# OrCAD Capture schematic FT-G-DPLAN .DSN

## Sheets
1 INDEX: size A; title: INDEX; rev: 1.11; note: 188C03322
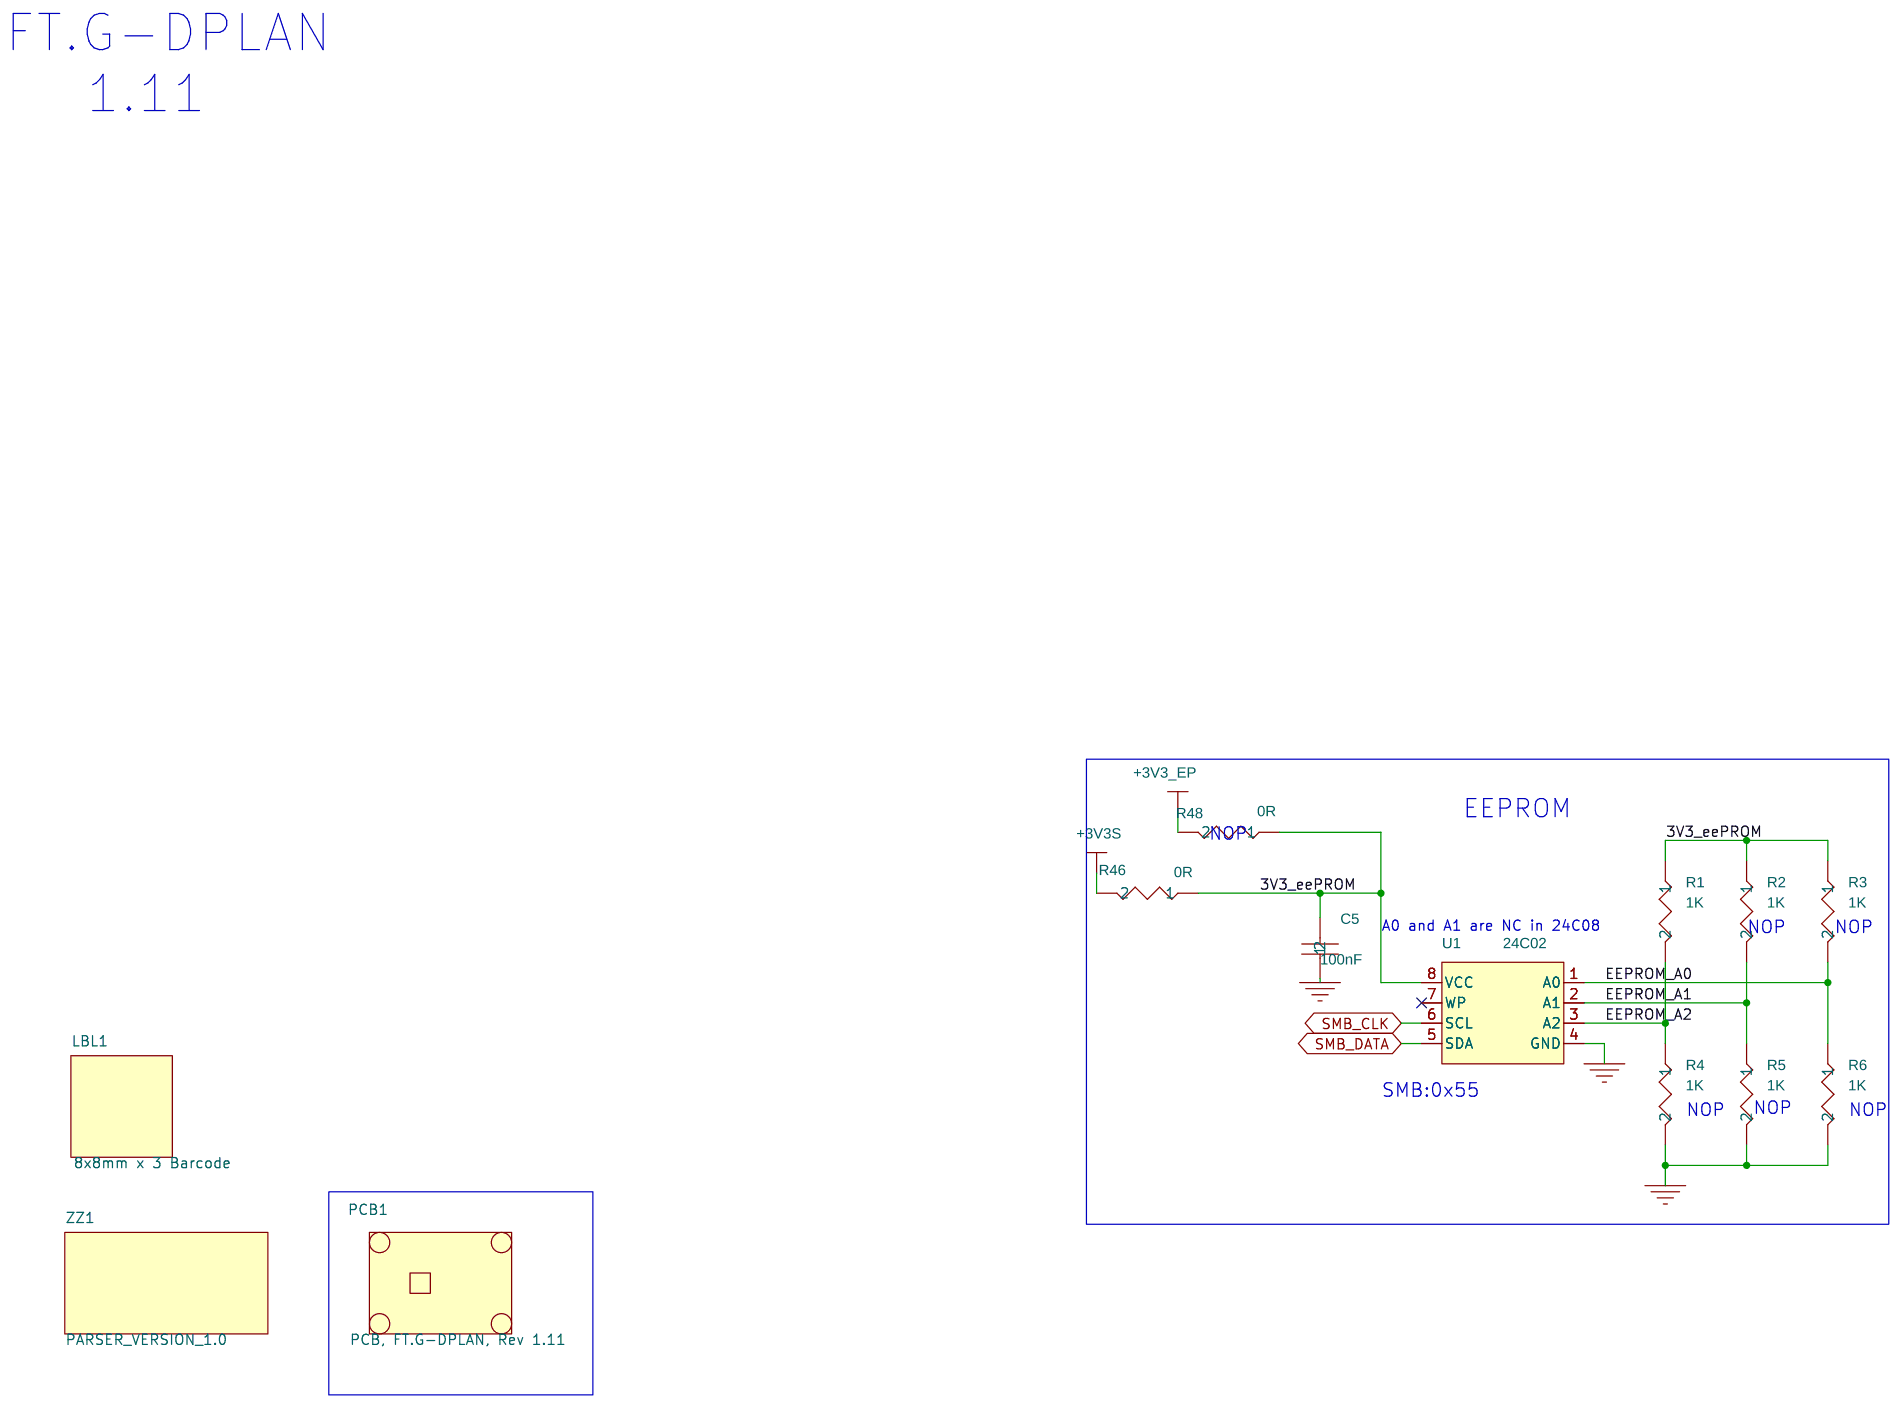
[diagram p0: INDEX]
2 Ribbon Conn.: size A; title: Ribbon Conn
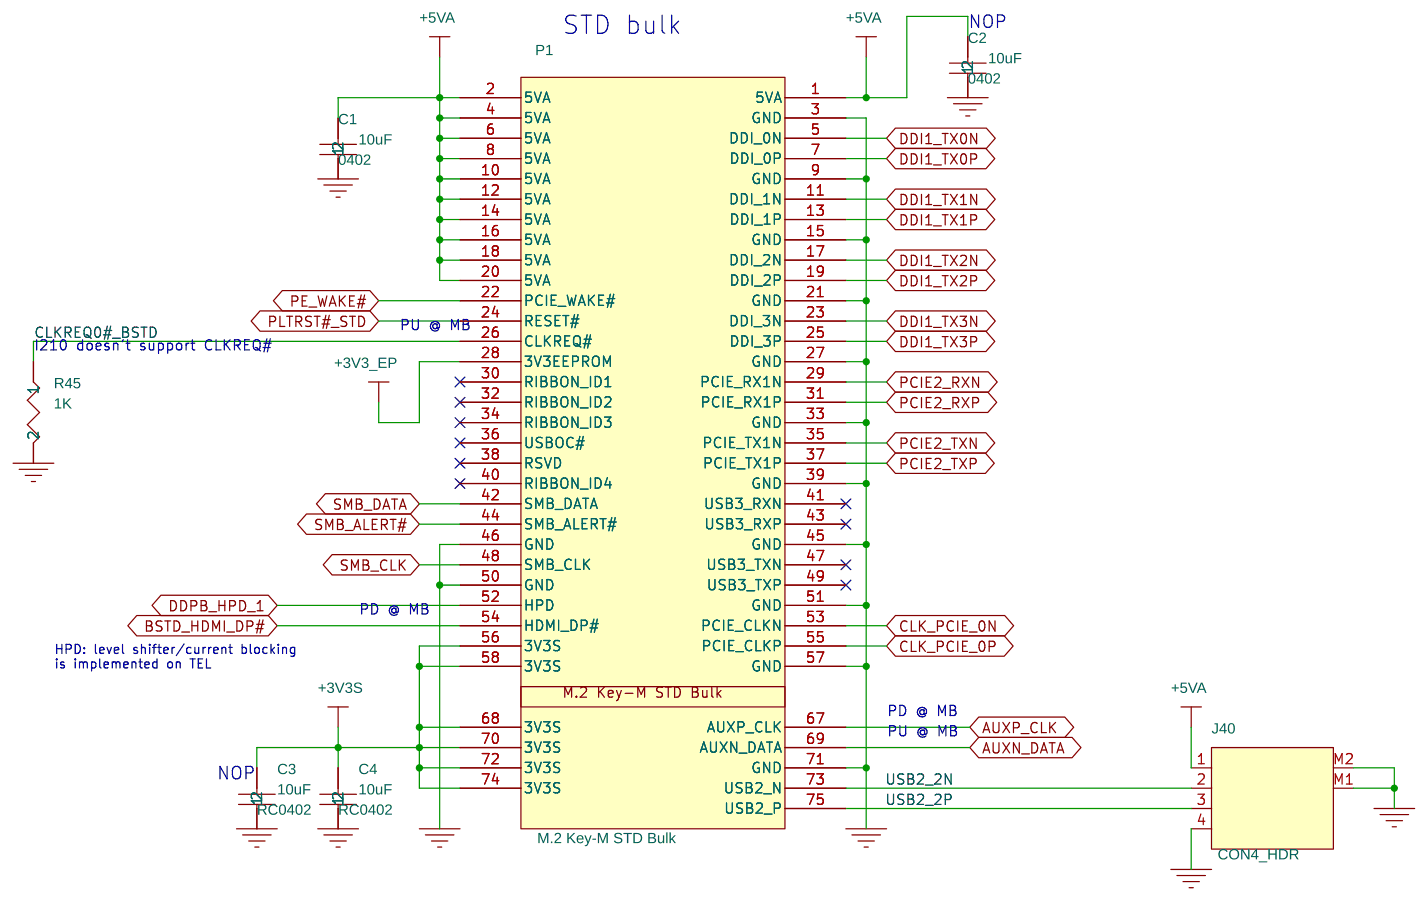
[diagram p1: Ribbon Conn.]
3 LAN: size A2; title: LAN
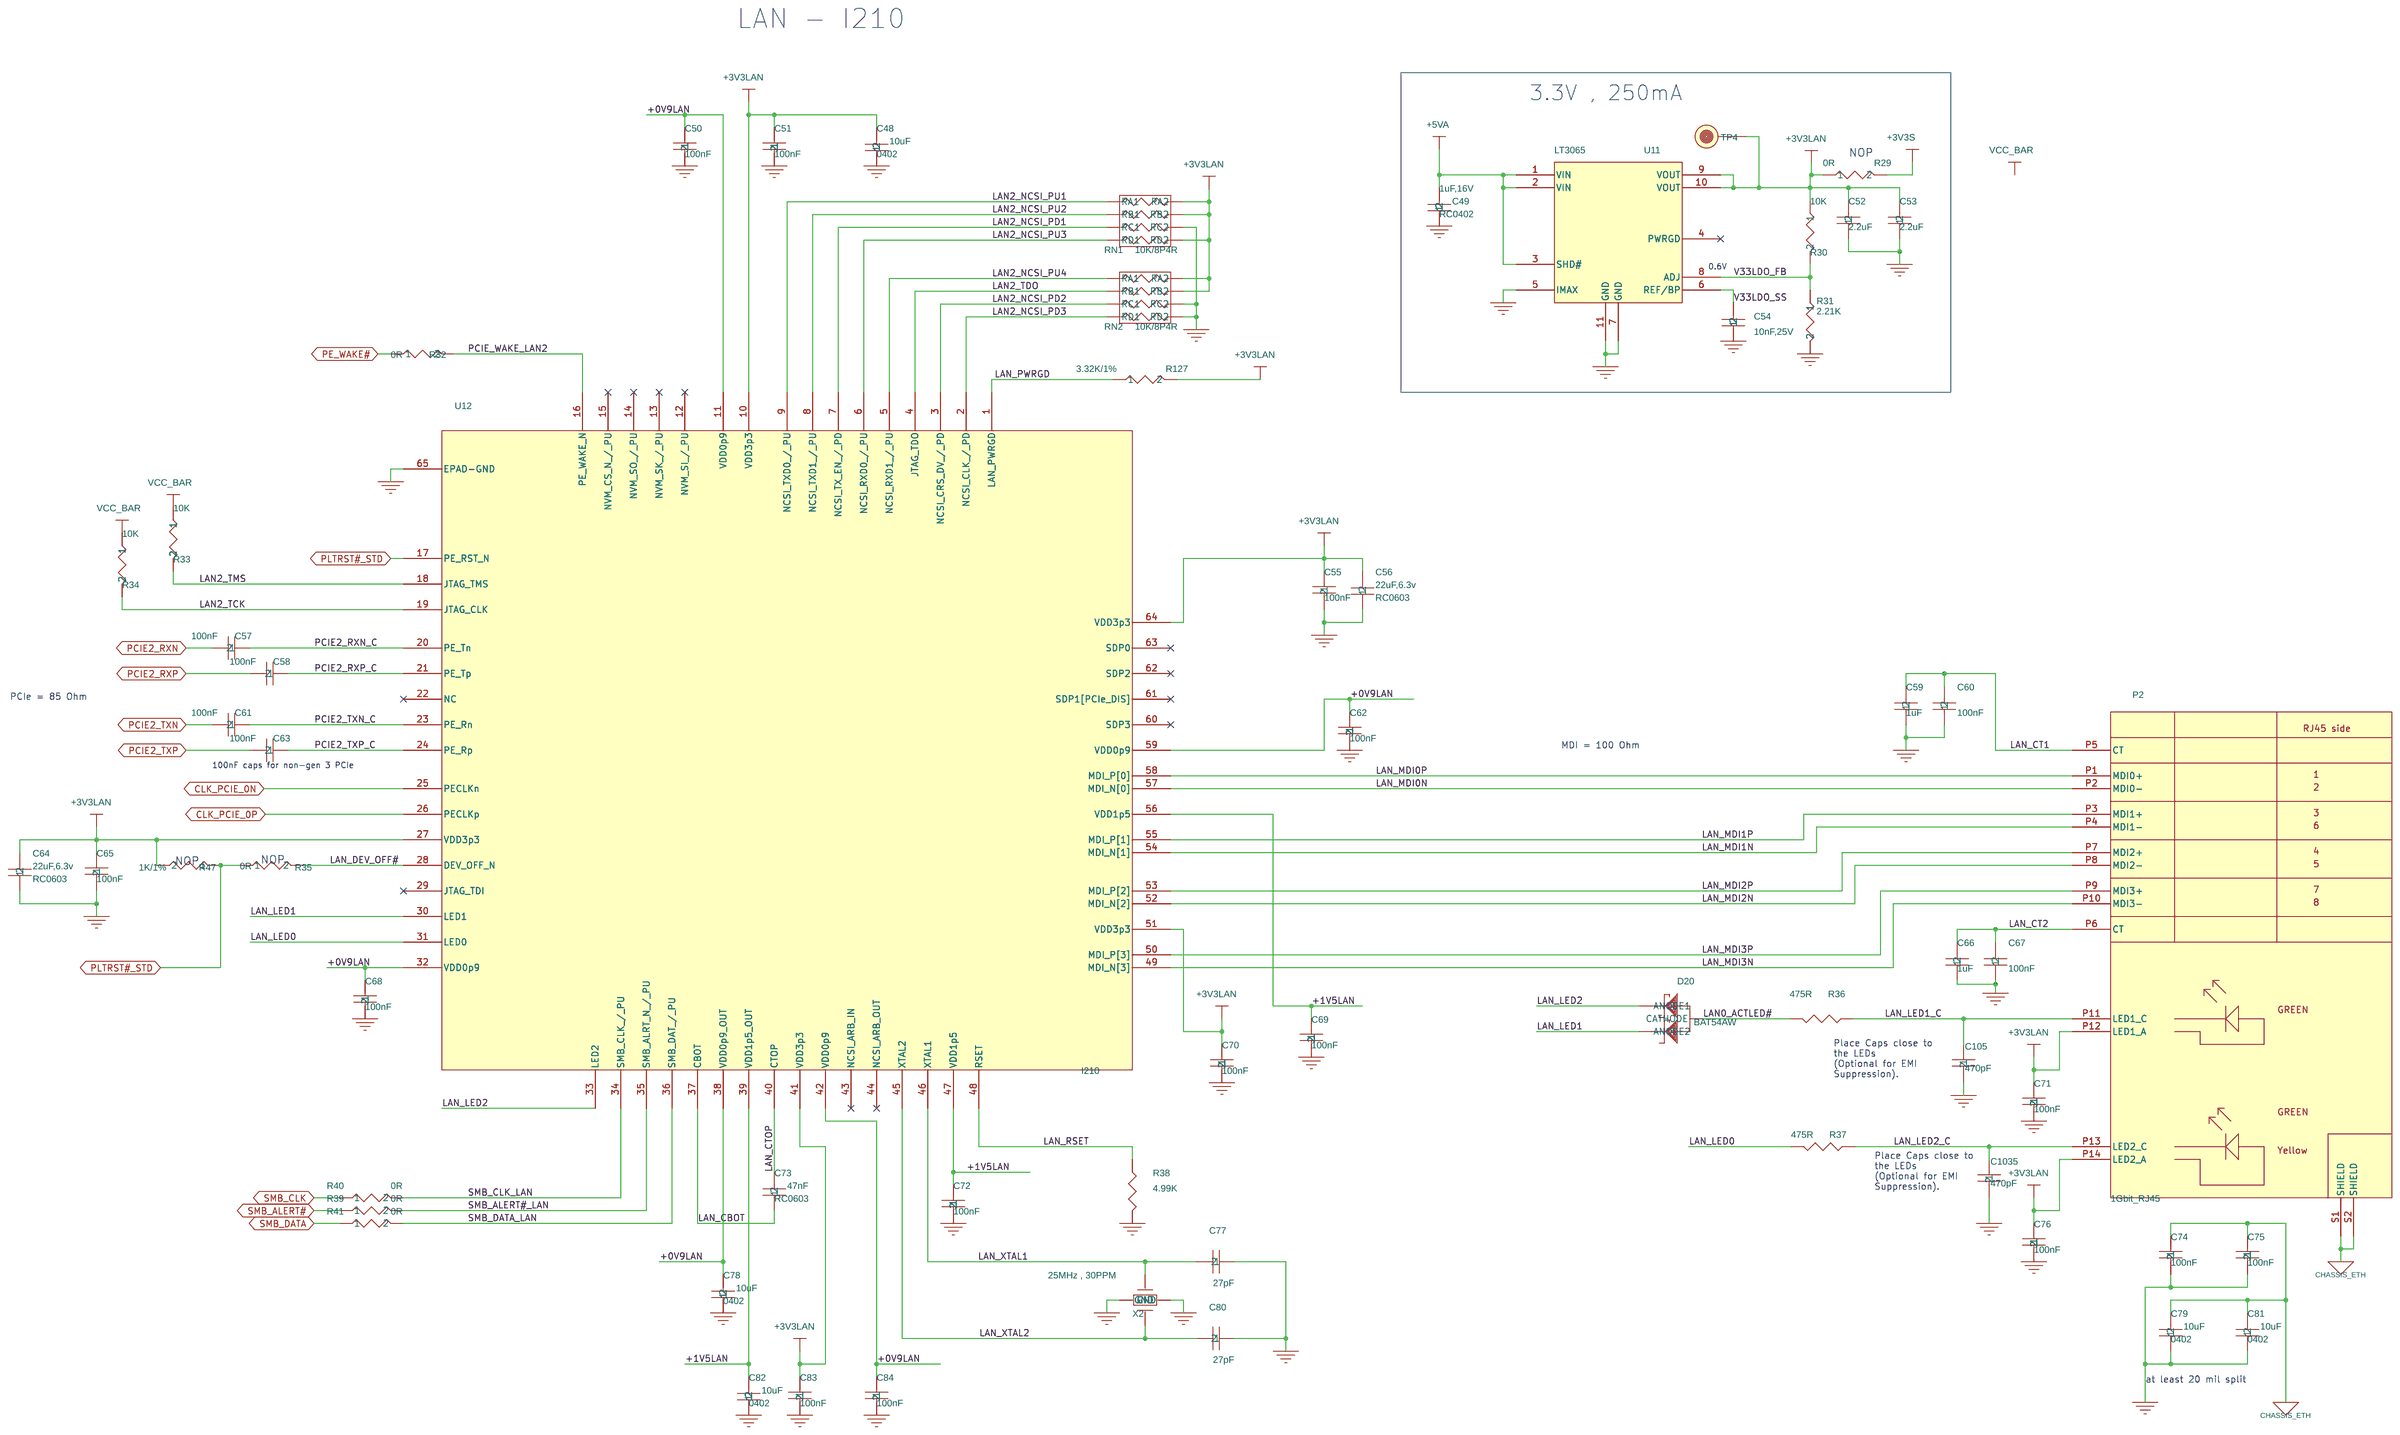
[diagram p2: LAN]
4 DP: size A4; title: DP
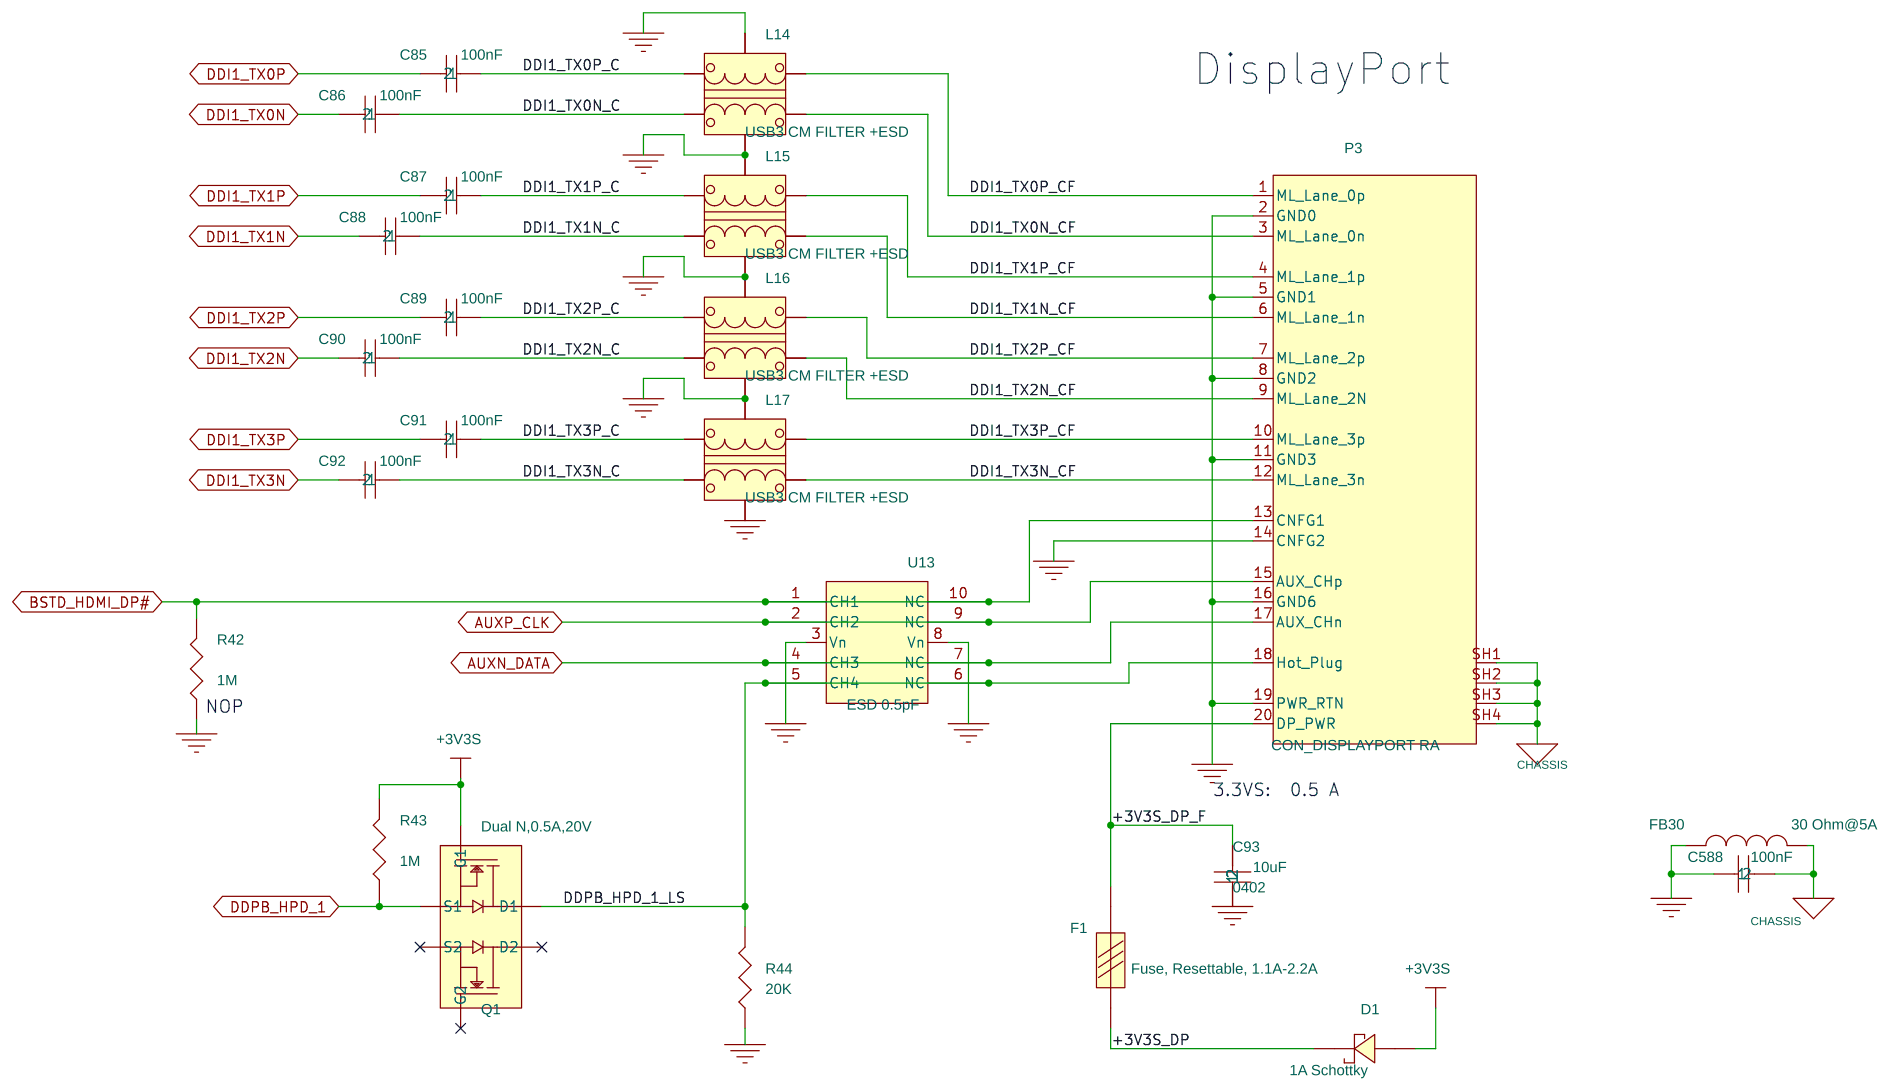
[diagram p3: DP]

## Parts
sheet DP
C85  100nF  [RC0402]
C86  100nF  [RC0402]
C87  100nF  [RC0402]
C88  100nF  [RC0402]
C89  100nF  [RC0402]
C90  100nF  [RC0402]
C91  100nF  [RC0402]
C92  100nF  [RC0402]
C93  10uF  [0402]
C588  100nF  [RC0402]
D1  1A Schottky  [SOD-123]
F1  Fuse, Resettable, 1.1A-2.2A  [FUSE-1206]
FB30  30 Ohm@5A  [FB0603]
L14  USB3 CM FILTER +ESD  [EMI1012-ESD]
L15  USB3 CM FILTER +ESD  [EMI1012-ESD]
L16  USB3 CM FILTER +ESD  [EMI1012-ESD]
L17  USB3 CM FILTER +ESD  [EMI1012-ESD]
P3  CON_DISPLAYPORT RA  [DP-F-RA-SM]
Q1  Dual N,0.5A,20V  [SOT-563-6]
R42  1M  [RC0402]
R43  1M  [RC0402]
R44  20K  [RC0402]
U13  ESD 0.5pF  [DFN-X2510D-10]
sheet INDEX
C5  100nF  [RC0402]
LBL1  8x8mm x 3 Barcode  [LBL XYU]
PCB1  PCB, FT.G-DPLAN, Rev 1.11
R1  1K  [RC0402]
R2  1K  [RC0402]
R3  1K  [RC0402]
R4  1K  [RC0402]
R5  1K  [RC0402]
R6  1K  [RC0402]
R46  0R  [RC0402]
R48  0R  [RC0402]
U1  24C02  [MO-229VCED-2]
ZZ1  PARSER_VERSION_1.0
sheet LAN
C48  10uF  [0402]
C49  1uF,16V  [RC0402]
C50  100nF  [RC0402]
C51  100nF  [RC0402]
C52  2.2uF  [RC0402]
C53  2.2uF  [RC0402]
C54  10nF,25V  [RC0402]
C55  100nF  [RC0402]
C56  22uF,6.3v  [RC0603]
C57  100nF  [RC0402]
C58  100nF  [RC0402]
C59  1uF  [RC0402]
C60  100nF  [RC0402]
C61  100nF  [RC0402]
C62  100nF  [RC0402]
C63  100nF  [RC0402]
C64  22uF,6.3v  [RC0603]
C65  100nF  [RC0402]
C66  1uF  [RC0402]
C67  100nF  [RC0402]
C68  100nF  [RC0402]
C69  100nF  [RC0402]
C70  100nF  [RC0402]
C71  100nF  [RC0402]
C72  100nF  [RC0402]
C73  47nF  [RC0603]
C74  100nF  [RC0402]
C75  100nF  [RC0402]
C76  100nF  [RC0402]
C77  27pF  [RC0402]
C78  10uF  [0402]
C79  10uF  [0402]
C80  27pF  [RC0402]
C81  10uF  [0402]
C82  10uF  [0402]
C83  100nF  [RC0402]
C84  100nF  [RC0402]
C105  470pF  [RC0603]
C1035  470pF  [RC0603]
D20  BAT54AW  [SOT323]
P2  1Gbit_RJ45  [DUSBRJ-1G]
R29  0R  [RC0402]
R30  10K  [RC0402]
R31  2.21K  [RC0402]
R32  0R  [RC0402]
R33  10K  [RC0402]
R34  10K  [RC0402]
R35  0R  [RC0402]
R36  475R  [RC0402]
R37  475R  [RC0402]
R38  4.99K  [RC0402]
R39  0R  [RC0402]
R40  0R  [RC0402]
R41  0R  [RC0402]
R47  1K/1%  [RC0402]
R127  3.32K/1%  [RC0402]
RN1  10K/8P4R  [RESNET8P0805]
RN2  10K/8P4R  [RESNET8P0805]
TP4  TP
U11  LT3065  [DFN3x3-10]
U12  I210  [QFN-64]
X2  25MHz , 30PPM  [OSC3225]
sheet Ribbon Conn.
C1  10uF  [0402]
C2  10uF  [0402]
C3  10uF  [RC0402]
C4  10uF  [RC0402]
J40  CON4_HDR  [1x4W2B1_25RASM]
P1  M.2 Key-M STD Bulk  [NGFF67P8HMkeySM]
R45  1K  [RC0402]

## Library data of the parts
C74 C85 = 15pF,_50V,_NPO,_5%,_0402_2: CLABCONF0: =FT-G-DPLAN; P/N: 151B10400S
C86 = 15pF,_50V,_NPO,_5%,_0402_5: CLABCONF0: =FT-G-DPLAN; P/N: 151B10400S
C75 C87 = 15pF,_50V,_NPO,_5%,_0402_6: CLABCONF0: =FT-G-DPLAN; P/N: 151B10400S
C76 C88 = 15pF,_50V,_NPO,_5%,_0402_7: CLABCONF0: =FT-G-DPLAN; P/N: 151B10400S
C5 C83 C89 = 15pF,_50V,_NPO,_5%,_0402: CLABCONF0: =FT-G-DPLAN; P/N: 151B10400S
C90 = 15pF,_50V,_NPO,_5%,_0402_1: CLABCONF0: =FT-G-DPLAN; P/N: 151B10400S
C72 C91 = 15pF,_50V,_NPO,_5%,_0402_3: CLABCONF0: =FT-G-DPLAN; P/N: 151B10400S
C71 C92 = 15pF,_50V,_NPO,_5%,_0402_4: CLABCONF0: =FT-G-DPLAN; P/N: 151B10400S
C4 C93 = 100nF,_10V,_X7R,_10%,_0402_1: CLABCONF0: =FT-G-DPLAN; P/N: 151B10600S
C588 = 100nF,_10V,_X7R,_10%,_0402: CLABCONF0: =FT-G-DPLAN
D1 = 1A_Schottky_Barrier_Rectifier: CLABCONF0: =FT-G-DPLAN
F1 = Fuse,_1.1_A_Ih,_2.2A_It: CLABCONF0: =FT-G-DPLAN
FB30 = Ferrite_bead_,_30_Ohm@5A: CLABCONF0: =FT-G-DPLAN
L14-L17 = USB3_CHOKE_+_ESD_FILTER: CLABCONF0: =FT-G-DPLAN; P/N: 142D11801S
P3 = CON_DISPLAYPORT-SINGLE_0: Con, DisplayPort single; CLABCONF0: =FT-G-DPLAN; P/N: 180K02000S
Q1 = DUAL_N-MOSFET,_0.5A_20V: CLABCONF0: =FT-G-DPLAN
R42 = RESISTOR: CLABCONF0: =NOP; P/N: 161C10045S
R43 = RESISTOR: CLABCONF0: =FT-G-DPLAN; P/N: 161C10045S
R44 = RESISTOR: CLABCONF0: =FT-G-DPLAN; P/N: 161C20021S
U13 = IC,ESD_Diode,0.25pF_,x4: CLABCONF0: =FT-G-DPLAN; P/N: 132D10020S
LBL1 = Label_8x8mm_x_3_for_Barcode: CLABCONF0: =FT-G-DPLAN; P/N: 374F09P20CU
PCB1 = SBC-iHSW_Rev_1.0: CLABCONF0: =FT-G-DPLAN; P/N: 188C03322
R1 = 348R,1%,0402,1_16W_1: CLABCONF0: =FT-G-DPLAN; P/N: 161C10011S
R2 = 348R,1%,0402,1_16W: CLABCONF0: =NOP; P/N: 161C10011S
R3 = 348R,1%,0402,1_16W_4: CLABCONF0: =NOP; P/N: 161C10011S
R4 = 348R,1%,0402,1_16W_5: CLABCONF0: =NOP; P/N: 161C10011S
R5 = 348R,1%,0402,1_16W_3: CLABCONF0: =NOP; P/N: 161C10011S
R6 = 348R,1%,0402,1_16W_2: CLABCONF0: =NOP; P/N: 161C10011S
R46 = 0R: CLABCONF0: =NOP; P/N: 161C00005S
R48 = 0R_1: CLABCONF0: =FT-G-DPLAN; P/N: 161C00005S
U1 = 24C02,_serial_EE,_2KB,_I2C: CLABCONF0: =FT-G-DPLAN; P/N: 111S31000S
ZZ1 = PARSER_VERSION_1.0: CLABCONF0: =FT-G-DPLAN
C48 = 100nF,_10V,_X7R,_10%,_0402_12: CLABCONF0: =FT-G-DPLAN; P/N: 151B10600S
C49 = 100nF,_10V,_X7R,_10%,_0402_1: CLABCONF0: =FT-G-DPLAN; P/N: 151C10500S
C50 = 15pF,_50V,_NPO,_5%,_0402_10: CLABCONF0: =FT-G-DPLAN; P/N: 151B10400S
C51 = 15pF,_50V,_NPO,_5%,_0402_15: CLABCONF0: =FT-G-DPLAN; P/N: 151B10400S
C52 = 100nF,_10V,_X7R,_10%,_0402_16: CLABCONF0: =FT-G-DPLAN; P/N: 151A22500S
C53 = 100nF,_10V,_X7R,_10%,_0402_13: CLABCONF0: =FT-G-DPLAN; P/N: 151A22500S
C54 = 100nF,_10V,_X7R,_10%,_0402_6: CLABCONF0: =FT-G-DPLAN; P/N: 151C10300S
C55 = 15pF,_50V,_NPO,_5%,_0402_11: CLABCONF0: =FT-G-DPLAN; P/N: 151B10400S
C56 = 100nF,_10V,_X7R,_10%,_0402: CLABCONF0: =FT-G-DPLAN; P/N: 151B22610S
C57 = 100nF,_10V,_X7R,_10%,_0402_7: CLABCONF0: =FT-G-DPLAN; P/N: 151B10400S
C58 = 100nF,_10V,_X7R,_10%,_0402_11: CLABCONF0: =FT-G-DPLAN; P/N: 151B10400S
C59 = 100nF,_10V,_X7R,_10%,_0402_18: CLABCONF0: =FT-G-DPLAN; P/N: 151C10500S
C60 = 100nF,_10V,_X7R,_10%,_0402_15: CLABCONF0: =FT-G-DPLAN; P/N: 151B10400S
C61 = 100nF,_10V,_X7R,_10%,_0402_4: CLABCONF0: =FT-G-DPLAN; P/N: 151B10400S
C62 = 15pF,_50V,_NPO,_5%,_0402_8: CLABCONF0: =FT-G-DPLAN; P/N: 151B10400S
C63 = 100nF,_10V,_X7R,_10%,_0402_9: CLABCONF0: =FT-G-DPLAN; P/N: 151B10400S
C64 = 100nF,_10V,_X7R,_10%,_0402_2: CLABCONF0: =FT-G-DPLAN; P/N: 151B22610S
C65 = 15pF,_50V,_NPO,_5%,_0402_12: CLABCONF0: =FT-G-DPLAN; P/N: 151B10400S
C66 = 100nF,_10V,_X7R,_10%,_0402_14: CLABCONF0: =FT-G-DPLAN; P/N: 151C10500S
C67 = 100nF,_10V,_X7R,_10%,_0402_19: CLABCONF0: =FT-G-DPLAN; P/N: 151B10400S
C68 = 15pF,_50V,_NPO,_5%,_0402_16: CLABCONF0: =FT-G-DPLAN; P/N: 151B10400S
C69 = 15pF,_50V,_NPO,_5%,_0402_13: CLABCONF0: =FT-G-DPLAN; P/N: 151B10400S
C70 = 15pF,_50V,_NPO,_5%,_0402_9: CLABCONF0: =FT-G-DPLAN; P/N: 151B10400S
C73 = 100nF,_10V,_X7R,_10%,_0402_8: CLABCONF0: =FT-G-DPLAN; P/N: 151C47310S
C77 = 15pF,_50V,_NPO,_5%,_0402_1: CLABCONF0: =FT-G-DPLAN; P/N: 151D27000S
C78 = 100nF,_10V,_X7R,_10%,_0402_5: CLABCONF0: =FT-G-DPLAN; P/N: 151B10600S
C79 = 100nF,_10V,_X7R,_10%,_0402_17: CLABCONF0: =FT-G-DPLAN; P/N: 151B10600S
C80 = 15pF,_50V,_NPO,_5%,_0402_5: CLABCONF0: =FT-G-DPLAN; P/N: 151D27000S
C81 = 100nF,_10V,_X7R,_10%,_0402_10: CLABCONF0: =FT-G-DPLAN; P/N: 151B10600S
C82 = 100nF,_10V,_X7R,_10%,_0402_3: CLABCONF0: =FT-G-DPLAN; P/N: 151B10600S
C84 = 15pF,_50V,_NPO,_5%,_0402_14: CLABCONF0: =FT-G-DPLAN; P/N: 151B10400S
C105 = 470pF,_50V,_X7R,_10%,_0603: CLABCONF0: =FT-G-DPLAN
C1035 = 470pF,_50V,_X7R,_10%,_0603_1: CLABCONF0: =FT-G-DPLAN
D20 = BAT54AW: CLABCONF0: =FT-G-DPLAN
P2 = Con_1.,1GBit_RJ45,_short: CLABCONF0: =FT-G-DPLAN; P/N: 182K01600
R29 = 0R_2: CLABCONF0: =NOP; P/N: 161C00005S
R30 = 0R_5: CLABCONF0: =FT-G-DPLAN; P/N: 161C10021S
R31 = 0R_4: CLABCONF0: =FT-G-DPLAN; P/N: 161C22111S
R32 = 0R_7: CLABCONF0: =FT-G-DPLAN; OriginalSymbolOrigin: 100uF
R33 = 0R_1: CLABCONF0: =FT-G-DPLAN; P/N: 161C10021S
R34 = 0R: CLABCONF0: =FT-G-DPLAN; P/N: 161C10021S
R35 = 0R_9: CLABCONF0: =NOP; OriginalSymbolOrigin: 100uF
R36 R37 = RESISTOR: CLABCONF0: =FT-G-DPLAN; P/N: 161C47501S
R38 = RESISTOR: CLABCONF0: =FT-G-DPLAN; P/N: 161C49911S
R39 = 0R_8: CLABCONF0: =FT-G-DPLAN
R40 = 0R_6: CLABCONF0: =FT-G-DPLAN
R41 = 0R_3: CLABCONF0: =FT-G-DPLAN; OriginalSymbolOrigin: 100uF
R47 = 1K,1%,0402,1_16W: CLABCONF0: =NOP
R127 = 3.32K,1%,0402,1_16W: CLABCONF0: =FT-G-DPLAN
RN1 RN2 = RN,10K,8P4R@0805: CLABCONF0: =FT-G-DPLAN
TP4 = TP_SMT: CLABCONF0: =NOP
U11 = LT3065_0: CLABCONF0: =FT-G-DPLAN; P/N: 123M0R601S
U12 = IC,_I211_I210_,LAN_CONTROLLER: CLABCONF0: =FT-G-DPLAN; P/N: 116B00071S
X2 = TMP_133032: CLABCONF0: =FT-G-DPLAN; P/N: 141B25603I
C1 = 100nF,_10V,_X7R,_10%,_0402: CLABCONF0: =FT-G-DPLAN; P/N: 151B10600S
C2 = 100nF,_10V,_X7R,_10%,_0402_3: CLABCONF0: =NOP; P/N: 151B10600S
C3 = 100nF,_10V,_X7R,_10%,_0402_2: CLABCONF0: =NOP; P/N: 151B10600S
J40 = CON4,W2B_,1.25mm: CLABCONF0: =FT-G-DPLAN
P1 = M.2_Key-M_STD_Bulk: CLABCONF0: =FT-G-DPLAN; P/N: 182K06700S
R45 = 348R,1%,0402,1_16W: CLABCONF0: =FT-G-DPLAN; P/N: 161C10011S

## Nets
3V3_eePROM: C5.2 R1.1 R2.1 R3.1 R46.1 R48.1 U1.8(VCC)
+0V9LAN: C50.1 C62.1 C68.1 C78.2 C84.1 U12.11(VDD0p9) U12.32(VDD0p9) U12.38(VDD0p9_OUT) U12.42(VDD0p9) U12.59(VDD0p9)
+1V5LAN: C69.1 C72.1 C82.2 U12.39(VDD1p5_OUT) U12.47(VDD1p5) U12.56(VDD1p5)
+3V3_EP: P1.28(3V3EEPROM) R48.2
+3V3LAN: C48.2 C51.1 C52.2 C53.2 C55.1 C56.2 C64.2 C65.1 C70.1 C71.1 C76.1 C83.1 P2.P12(LED1_A) P2.P14(LED2_A) R29.1 R30.1 R33.1 R34.1 R47.2 R127.2 RN1.5(RD2) RN1.7(RB2) RN1.8(RA2) RN2.7(RB2) RN2.8(RA2) TP4.1 U11.9(VOUT) U11.10(VOUT) U12.10(VDD3p3) U12.27(VDD3p3) U12.41(VDD3p3) U12.51(VDD3p3) U12.64(VDD3p3)
+3V3S: C3.2 C4.2 D1.2(ANODE) P1.56(3V3S) P1.58(3V3S) P1.68(3V3S) P1.70(3V3S) P1.72(3V3S) P1.74(3V3S) Q1.2(G1) R29.2 R43.2 R46.2
+3V3S_DP: D1.1(CATHODE) F1.2
+3V3S_DP_F: C93.2 F1.1 P3.20(DP_PWR)
+5VA: C1.2 C2.2 C49.2 J40.1 P1.1(5VA) P1.2(5VA) P1.4(5VA) P1.6(5VA) P1.8(5VA) P1.10(5VA) P1.12(5VA) P1.14(5VA) P1.16(5VA) P1.18(5VA) P1.20(5VA) U11.1(VIN) U11.2(VIN) U11.3(SHD#)
GND: C1.1 C2.1 C3.1 C4.1 C5.1 C48.1 C49.1 C50.2 C51.2 C52.1 C53.1 C54.1 C55.2 C56.1 C59.1 C60.1 C62.2 C64.1 C65.2 C66.1 C67.1 C68.2 C69.2 C70.2 C71.2 C72.2 C74.2 C75.2 C76.2 C77.1 C78.1 C79.1 C80.1 C81.1 C82.1 C83.2 C84.2 C93.1 C105.2 C588.1 C1035.2 FB30.1 J40.4 J40.M1 J40.M2 L14.5 L14.6 L15.5 L15.6 L16.5 L16.6 L17.5 L17.6 P1.3(GND) P1.9(GND) P1.15(GND) P1.21(GND) P1.27(GND) P1.33(GND) P1.39(GND) P1.45(GND) P1.46(GND) P1.50(GND) P1.51(GND) P1.57(GND) P1.71(GND) P3.2(GND0) P3.5(GND1) P3.8(GND2) P3.11(GND3) P3.14(CNFG2) P3.16(GND6) P3.19(PWR_RTN) R4.2 R5.2 R6.2 R31.2 R38.2 R42.1 R44.1 R45.2 RN1.6(RC2) RN2.5(RD2) RN2.6(RC2) U1.4(GND) U11.5(IMAX) U11.7(GND) U11.11(GND) U12.65(EPAD-GND) U13.3(Vn) U13.8(Vn) X2.2(GND) X2.4(GND)
V33LDO_FB: R30.2 R31.1 U11.8(ADJ)
V33LDO_SS: C54.2 U11.6(REF/BP)
AUXN_DATA: P1.69(AUXN_DATA) P3.17(AUX_CHn) U13.4(CH3) U13.7(NC)
AUXP_CLK: P1.67(AUXP_CLK) P3.15(AUX_CHp) U13.2(CH2) U13.9(NC)
BSTD_HDMI_DP#: P1.54(HDMI_DP#) P3.13(CNFG1) R42.2 U13.1(CH1) U13.10(NC)
CHASSIS: C588.2 FB30.2 P3.SH1 P3.SH2 P3.SH3 P3.SH4
CHASSIS_ETH: C74.1 C75.1 C79.2 C81.2 P2.S1(SHIELD) P2.S2(SHIELD)
CLK_PCIE_0N: P1.53(PCIE_CLKN) U12.25(PECLKn)
CLK_PCIE_0P: P1.55(PCIE_CLKP) U12.26(PECLKp)
CLKREQ0#_BSTD: P1.26(CLKREQ#) R45.1
DDI1_TX0N: C86.2 P1.5(DDI_0N)
DDI1_TX0N_C: C86.1 L14.3
DDI1_TX0N_CF: L14.2 P3.3(ML_Lane_0n)
DDI1_TX0P: C85.2 P1.7(DDI_0P)
DDI1_TX0P_C: C85.1 L14.4
DDI1_TX0P_CF: L14.1 P3.1(ML_Lane_0p)
DDI1_TX1N: C88.2 P1.11(DDI_1N)
DDI1_TX1N_C: C88.1 L15.3
DDI1_TX1N_CF: L15.2 P3.6(ML_Lane_1n)
DDI1_TX1P: C87.2 P1.13(DDI_1P)
DDI1_TX1P_C: C87.1 L15.4
DDI1_TX1P_CF: L15.1 P3.4(ML_Lane_1p)
DDI1_TX2N: C90.2 P1.17(DDI_2N)
DDI1_TX2N_C: C90.1 L16.3
DDI1_TX2N_CF: L16.2 P3.9(ML_Lane_2N)
DDI1_TX2P: C89.2 P1.19(DDI_2P)
DDI1_TX2P_C: C89.1 L16.4
DDI1_TX2P_CF: L16.1 P3.7(ML_Lane_2p)
DDI1_TX3N: C92.2 P1.23(DDI_3N)
DDI1_TX3N_C: C92.1 L17.3
DDI1_TX3N_CF: L17.2 P3.12(ML_Lane_3n)
DDI1_TX3P: C91.2 P1.25(DDI_3P)
DDI1_TX3P_C: C91.1 L17.4
DDI1_TX3P_CF: L17.1 P3.10(ML_Lane_3p)
DDPB_HPD_1: P1.52(HPD) Q1.1(S1) R43.1
DDPB_HPD_1_LS: P3.18(Hot_Plug) Q1.6(D1) R44.2 U13.5(CH4) U13.6(NC)
EEPROM_A0: R3.2 R6.1 U1.1(A0)
EEPROM_A1: R2.2 R5.1 U1.2(A1)
EEPROM_A2: R1.2 R4.1 U1.3(A2)
LAN0_ACTLED#: D20.3(CATHODE) R36.2
LAN2_NCSI_PD1: RN1.3(RC1) U12.7(NCSI_TX_EN_/_PD)
LAN2_NCSI_PD2: RN2.3(RC1) U12.3(NCSI_CRS_DV_/_PD)
LAN2_NCSI_PD3: RN2.4(RD1) U12.2(NCSI_CLK_/_PD)
LAN2_NCSI_PU1: RN1.1(RA1) U12.9(NCSI_TXD0_/_PU)
LAN2_NCSI_PU2: RN1.2(RB1) U12.8(NCSI_TXD1_/_PU)
LAN2_NCSI_PU3: RN1.4(RD1) U12.6(NCSI_RXD0_/_PU)
LAN2_NCSI_PU4: RN2.1(RA1) U12.5(NCSI_RXD1_/_PU)
LAN2_TCK: R34.2 U12.19(JTAG_CLK)
LAN2_TDO: RN2.2(RB1) U12.4(JTAG_TDO)
LAN2_TMS: R33.2 U12.18(JTAG_TMS)
LAN_CBOT: C73.1 U12.37(CBOT)
LAN_CT1: C59.2 C60.2 P2.P5(CT)
LAN_CT2: C66.2 C67.2 P2.P6(CT)
LAN_CTOP: C73.2 U12.40(CTOP)
LAN_DEV_OFF#: R35.2 U12.28(DEV_OFF_N)
LAN_LED0: R37.2 U12.31(LED0)
LAN_LED1: D20.2(ANODE2) U12.30(LED1)
LAN_LED1_C: C105.1 P2.P11(LED1_C) R36.1
LAN_LED2: D20.1(ANODE1) U12.33(LED2)
LAN_LED2_C: C1035.1 P2.P13(LED2_C) R37.1
LAN_MDI0N: P2.P2(MDI0-) U12.57(MDI_N[0])
LAN_MDI0P: P2.P1(MDI0+) U12.58(MDI_P[0])
LAN_MDI1N: P2.P4(MDI1-) U12.54(MDI_N[1])
LAN_MDI1P: P2.P3(MDI1+) U12.55(MDI_P[1])
LAN_MDI2N: P2.P8(MDI2-) U12.52(MDI_N[2])
LAN_MDI2P: P2.P7(MDI2+) U12.53(MDI_P[2])
LAN_MDI3N: P2.P10(MDI3-) U12.49(MDI_N[3])
LAN_MDI3P: P2.P9(MDI3+) U12.50(MDI_P[3])
LAN_PWRGD: R127.1 U12.1(LAN_PWRGD)
LAN_RSET: R38.1 U12.48(RSET)
LAN_XTAL1: C77.2 U12.46(XTAL1) X2.1
LAN_XTAL2: C80.2 U12.45(XTAL2) X2.3
PCIE2_RXN: C57.2 P1.29(PCIE_RX1N)
PCIE2_RXN_C: C57.1 U12.20(PE_Tn)
PCIE2_RXP: C58.2 P1.31(PCIE_RX1P)
PCIE2_RXP_C: C58.1 U12.21(PE_Tp)
PCIE2_TXN: C61.2 P1.35(PCIE_TX1N)
PCIE2_TXN_C: C61.1 U12.23(PE_Rn)
PCIE2_TXP: C63.2 P1.37(PCIE_TX1P)
PCIE2_TXP_C: C63.1 U12.24(PE_Rp)
PCIE_WAKE_LAN2: R32.2 U12.16(PE_WAKE_N)
PE_WAKE#: P1.22(PCIE_WAKE#) R32.1
PLTRST#_STD: P1.24(RESET#) R35.1 R47.1 U12.17(PE_RST_N)
SMB_ALERT#: P1.44(SMB_ALERT#) R39.1
SMB_ALERT#_LAN: R39.2 U12.35(SMB_ALRT_N_/_PU)
SMB_CLK: P1.48(SMB_CLK) R40.1 U1.6(SCL)
SMB_CLK_LAN: R40.2 U12.34(SMB_CLK_/_PU)
SMB_DATA: P1.42(SMB_DATA) R41.1 U1.5(SDA)
SMB_DATA_LAN: R41.2 U12.36(SMB_DAT_/_PU)
USB2_2N: J40.2 P1.73(USB2_N)
USB2_2P: J40.3 P1.75(USB2_P)

Not connected (* = marked no-connect by the designer): P1 30(RIBBON_ID1)* 32(RIBBON_ID2)* 34(RIBBON_ID3)* 36(USBOC#)* 38(RSVD)* 40(RIBBON_ID4)* 41(USB3_RXN)* 43(USB3_RXP)* 47(USB3_TXN)* 49(USB3_TXP)*; Q1 3(D2)* 4(S2)* 5(G2)*; U1 7(WP)*; U11 4(PWRGD)*; U12 12(NVM_SI_/_PU)* 13(NVM_SK_/_PU)* 14(NVM_SO_/_PU)* 15(NVM_CS_N_/_PU)* 22(NC)* 29(JTAG_TDI)* 43(NCSI_ARB_IN)* 44(NCSI_ARB_OUT)* 60(SDP3)* 61(SDP1[PCIe_DIS])* 62(SDP2)* 63(SDP0)*

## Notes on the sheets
sheet 1
- FT.G-DPLAN
- 1.11
- EEPROM
- NOP
- A0 and A1 are NC in 24C08
- NOP
- NOP
- SMB:0x55
- NOP
- NOP
- NOP
sheet 2
- STD bulk
- NOP
- PU @ MB
- I210 doesn't support CLKREQ#
- PD @ MB
- HPD: level shifter/current blocking
  is implemented on TEL
- PD @ MB
- PU @ MB
- NOP
sheet 3
- LAN - I210
- 3.3V , 250mA
- NOP
- 0.6V
- PCIe = 85 Ohm
- MDI = 100 Ohm
- 100nF caps for non-gen 3 PCIe
- NOP
- NOP
- Place Caps close to
  the LEDs
  (Optional for EMI
  Suppression).
- Place Caps close to
  the LEDs
  (Optional for EMI
  Suppression).
- at least 20 mil split
sheet 4
- DisplayPort
- NOP
- 3.3VS:  0.5 A
